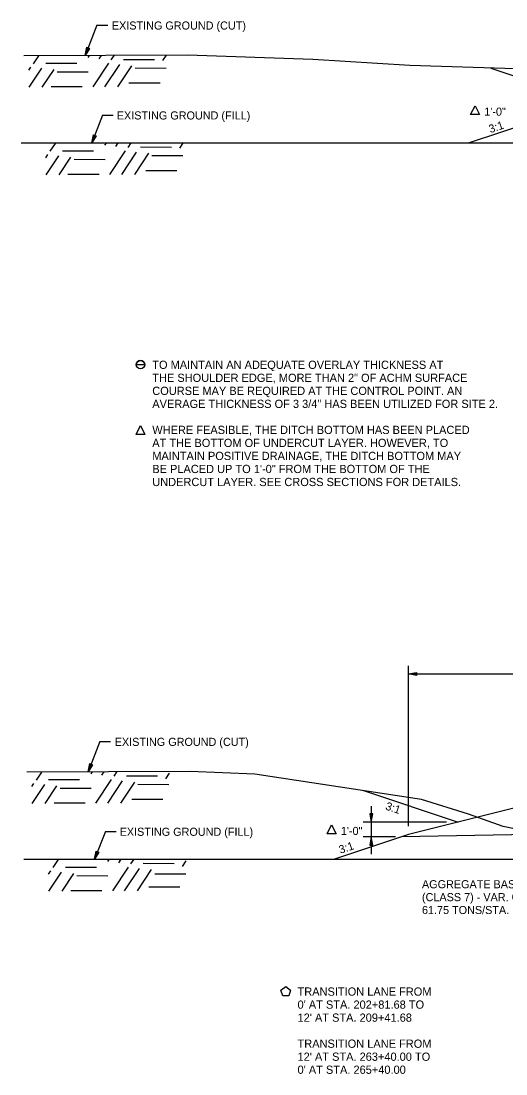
# Model space of a CAD drawing. Extents: x 1398565 to 1398920, y 1968324 to 1968581.
# Drawn here: x 1398565.6 to 1398600.9, y 1968324.5 to 1968401.3 of the extents above; entities that cross this region are included whole.
import ezdxf

# ---------------------------------------------------------------- set-up
doc = ezdxf.new("R2010")
doc.units = 0
for name, color, linetype in [('10', 7, 'Continuous'), ('19', 7, 'Continuous'), ('42', 7, 'Continuous'), ('9', 7, 'Continuous'), ('Default', 7, 'Continuous')]:
    doc.layers.add(name, color=color, linetype=linetype)

msp = doc.modelspace()

# ---------------------------------------------------------------- linework, layer by layer
at = {"layer": '10'}
msp.add_line((1398573.963, 1968376.246), (1398574.574, 1968376.246), dxfattribs=at)
for points in [[(1398598.655, 1968395.138), (1398598.975, 1968394.497), (1398598.334, 1968394.497)], [(1398574.272, 1968371.802), (1398574.592, 1968371.16), (1398573.951, 1968371.16)], [(1398588.201, 1968342.662), (1398588.521, 1968342.021), (1398587.88, 1968342.021)], [(1398584.51, 1968330.615), (1398584.859, 1968330.869), (1398585.208, 1968330.615), (1398585.075, 1968330.204), (1398584.643, 1968330.204)]]:
    msp.add_lwpolyline(points, close=True, dxfattribs=at)
msp.add_circle((1398574.268, 1968376.246), 0.306, dxfattribs=at)
msp.add_arc((1398574.268, 1968376.246), 0.306, 0, 180, dxfattribs=at)
at = {"layer": '19'}
for p, q in [((1398571.097, 1968401.005), (1398570.24, 1968398.803)), ((1398571.097, 1968401.005), (1398571.879, 1968401.005)), ((1398570.24, 1968398.803), (1398570.36, 1968399.4)), ((1398570.556, 1968399.324), (1398570.24, 1968398.803)), ((1398570.284, 1968398.958), (1398570.411, 1968399.38)), ((1398570.509, 1968399.342), (1398570.312, 1968398.947)), ((1398570.36, 1968399.4), (1398570.556, 1968399.324)), ((1398599.796, 1968397.888), (1398607.436, 1968395.342)), ((1398605.586, 1968394.879), (1398598.222, 1968392.424)), ((1398571.498, 1968394.445), (1398570.713, 1968392.425)), ((1398571.498, 1968394.445), (1398572.281, 1968394.445)), ((1398570.713, 1968392.425), (1398570.832, 1968393.022)), ((1398571.028, 1968392.946), (1398570.713, 1968392.425)), ((1398570.757, 1968392.579), (1398570.884, 1968393.002)), ((1398570.981, 1968392.964), (1398570.785, 1968392.569)), ((1398570.832, 1968393.022), (1398571.028, 1968392.946)), ((1398593.795, 1968342.574), (1398593.795, 1968354.28)), ((1398593.795, 1968353.68), (1398594.395, 1968353.785)), ((1398593.795, 1968353.68), (1398617.795, 1968353.68)), ((1398594.395, 1968353.575), (1398593.795, 1968353.68)), ((1398593.955, 1968353.695), (1398594.395, 1968353.73)), ((1398594.395, 1968353.625), (1398593.955, 1968353.665)), ((1398594.395, 1968353.785), (1398594.395, 1968353.575)), ((1398571.306, 1968348.742), (1398570.449, 1968346.54)), ((1398571.306, 1968348.742), (1398572.088, 1968348.742)), ((1398570.449, 1968346.54), (1398570.569, 1968347.138)), ((1398570.765, 1968347.061), (1398570.449, 1968346.54)), ((1398570.493, 1968346.695), (1398570.62, 1968347.118)), ((1398570.718, 1968347.08), (1398570.521, 1968346.684)), ((1398570.569, 1968347.138), (1398570.765, 1968347.061)), ((1398611.795, 1968346.458), (1398593.795, 1968341.958)), ((1398590.516, 1968345.169), (1398597.427, 1968342.866)), ((1398591.195, 1968343.466), (1398590.985, 1968343.466)), ((1398590.985, 1968343.466), (1398591.09, 1968342.866)), ((1398591.04, 1968343.466), (1398591.075, 1968343.026)), ((1398591.09, 1968344.023), (1398591.09, 1968342.748)), ((1398591.09, 1968342.866), (1398591.195, 1968343.466)), ((1398591.105, 1968343.026), (1398591.145, 1968343.466)), ((1398591.09, 1968342.748), (1398591.09, 1968340.542)), ((1398642.795, 1968342.782), (1398593.298, 1968341.792)), ((1398571.707, 1968342.182), (1398570.921, 1968340.162)), ((1398571.707, 1968342.182), (1398572.49, 1968342.182)), ((1398593.795, 1968341.958), (1398588.407, 1968340.162)), ((1398591.09, 1968341.792), (1398590.985, 1968341.192)), ((1398590.985, 1968341.192), (1398591.195, 1968341.192)), ((1398591.075, 1968341.632), (1398591.04, 1968341.192)), ((1398591.195, 1968341.192), (1398591.09, 1968341.792)), ((1398591.145, 1968341.192), (1398591.105, 1968341.632)), ((1398570.921, 1968340.162), (1398571.041, 1968340.759)), ((1398571.237, 1968340.683), (1398570.921, 1968340.162)), ((1398570.965, 1968340.317), (1398571.092, 1968340.739)), ((1398571.19, 1968340.701), (1398570.993, 1968340.306)), ((1398571.041, 1968340.759), (1398571.237, 1968340.683))]:
    msp.add_line(p, q, dxfattribs=at)
at = {"layer": '42'}
for points in [[(1398565.563, 1968392.424), (1398612.06, 1968392.424), (1398636.586, 1968398.534), (1398642.586, 1968398.774)], [(1398615.319, 1968393.236), (1398605.766, 1968396.82), (1398601.609, 1968397.832), (1398593.902, 1968398.071), (1398586.821, 1968398.502), (1398577.688, 1968398.831), (1398565.772, 1968398.786)], [(1398565.772, 1968340.162), (1398612.268, 1968340.162), (1398636.795, 1968346.271), (1398642.795, 1968346.511)], [(1398612.268, 1968340.162), (1398600.713, 1968342.553), (1398598.177, 1968343.459), (1398594.756, 1968344.524), (1398582.596, 1968346.375), (1398577.897, 1968346.568), (1398565.981, 1968346.523)]]:
    msp.add_lwpolyline(points, dxfattribs=at)
at = {"layer": '9'}
for p, q in [((1398566.469, 1968398.203), (1398566.858, 1968398.786)), ((1398570.453, 1968398.652), (1398570.556, 1968398.807)), ((1398571.251, 1968398.564), (1398571.416, 1968398.812)), ((1398572.141, 1968398.476), (1398572.368, 1968398.817)), ((1398575.905, 1968398.442), (1398576.169, 1968398.838)), ((1398566.131, 1968397.731), (1398566.285, 1968397.961)), ((1398567.359, 1968398.246), (1398569.621, 1968398.24)), ((1398570.81, 1968396.514), (1398571.957, 1968398.234)), ((1398571.67, 1968396.519), (1398572.755, 1968398.146)), ((1398572.623, 1968396.524), (1398573.645, 1968398.058)), ((1398573.031, 1968398.518), (1398575.293, 1968398.513)), ((1398573.869, 1968397.892), (1398576.131, 1968397.886)), ((1398566.16, 1968396.488), (1398567.083, 1968397.873)), ((1398567.112, 1968396.493), (1398567.973, 1968397.785)), ((1398568.197, 1968397.62), (1398570.459, 1968397.614)), ((1398567.758, 1968396.541), (1398570.02, 1968396.536)), ((1398573.43, 1968396.814), (1398575.692, 1968396.808)), ((1398567.696, 1968391.812), (1398568.084, 1968392.394)), ((1398568.585, 1968391.854), (1398570.847, 1968391.848)), ((1398571.679, 1968392.261), (1398571.782, 1968392.415)), ((1398572.037, 1968390.122), (1398573.184, 1968391.842)), ((1398572.477, 1968392.172), (1398572.642, 1968392.42)), ((1398572.897, 1968390.127), (1398573.981, 1968391.754)), ((1398573.368, 1968392.085), (1398573.595, 1968392.425)), ((1398574.257, 1968392.127), (1398576.519, 1968392.121)), ((1398577.132, 1968392.05), (1398577.396, 1968392.446)), ((1398567.358, 1968391.339), (1398567.512, 1968391.57)), ((1398567.386, 1968390.096), (1398568.31, 1968391.481)), ((1398568.339, 1968390.101), (1398569.2, 1968391.394)), ((1398569.423, 1968391.228), (1398571.685, 1968391.222)), ((1398573.849, 1968390.132), (1398574.872, 1968391.666)), ((1398575.095, 1968391.501), (1398577.357, 1968391.495)), ((1398574.656, 1968390.422), (1398576.918, 1968390.417)), ((1398568.984, 1968390.15), (1398571.246, 1968390.144)), ((1398566.678, 1968345.941), (1398567.067, 1968346.523)), ((1398570.662, 1968346.39), (1398570.765, 1968346.544)), ((1398571.46, 1968346.301), (1398571.625, 1968346.549)), ((1398572.35, 1968346.213), (1398572.577, 1968346.554)), ((1398576.114, 1968346.033), (1398576.378, 1968346.43)), ((1398566.34, 1968345.468), (1398566.494, 1968345.699)), ((1398567.568, 1968345.983), (1398569.83, 1968345.977)), ((1398571.019, 1968344.251), (1398572.166, 1968345.971)), ((1398571.879, 1968344.256), (1398572.964, 1968345.883)), ((1398572.832, 1968344.261), (1398573.854, 1968345.795)), ((1398573.24, 1968346.256), (1398575.502, 1968346.25)), ((1398566.369, 1968344.225), (1398567.292, 1968345.61)), ((1398567.321, 1968344.23), (1398568.182, 1968345.522)), ((1398568.406, 1968345.357), (1398570.668, 1968345.351)), ((1398574.078, 1968345.63), (1398576.339, 1968345.624)), ((1398567.967, 1968344.279), (1398570.229, 1968344.273)), ((1398573.639, 1968344.551), (1398575.9, 1968344.545)), ((1398567.905, 1968339.549), (1398568.293, 1968340.132)), ((1398568.794, 1968339.591), (1398571.056, 1968339.585)), ((1398571.888, 1968339.998), (1398571.991, 1968340.152)), ((1398572.246, 1968337.859), (1398573.392, 1968339.58)), ((1398572.686, 1968339.909), (1398572.851, 1968340.157)), ((1398573.576, 1968339.822), (1398573.804, 1968340.162)), ((1398574.466, 1968339.864), (1398576.728, 1968339.858)), ((1398577.34, 1968339.641), (1398577.605, 1968340.038)), ((1398567.567, 1968339.076), (1398567.721, 1968339.307)), ((1398567.595, 1968337.833), (1398568.518, 1968339.218)), ((1398568.547, 1968337.839), (1398569.409, 1968339.131)), ((1398569.632, 1968338.965), (1398571.894, 1968338.959)), ((1398573.106, 1968337.864), (1398574.19, 1968339.491)), ((1398574.058, 1968337.869), (1398575.081, 1968339.404)), ((1398575.304, 1968339.092), (1398577.566, 1968339.086)), ((1398574.865, 1968338.16), (1398577.127, 1968338.154)), ((1398569.193, 1968337.887), (1398571.455, 1968337.881))]:
    msp.add_line(p, q, dxfattribs=at)
at = {"layer": 'Default'}
for p, q in [((1398596.583, 1968342.866), (1398590.495, 1968342.866)), ((1398592.862, 1968341.792), (1398590.509, 1968341.792))]:
    msp.add_line(p, q, dxfattribs=at)

# ---------------------------------------------------------------- texts
at = {"layer": '10'}
for s, height, rotation, p in [('EXISTING GROUND (CUT)', 0.59001, 360, (1398572.181, 1968400.694)), ('1\'-0"', 0.59, 360, (1398599.329, 1968394.41)), ('EXISTING GROUND (FILL)', 0.59001, 360, (1398572.54, 1968394.134)), ('3:1', 0.59, 18.49392, (1398599.77, 1968393.135)), ('EXISTING GROUND (CUT)', 0.59001, 360, (1398572.389, 1968348.431)), ('3:1', 0.59, 341.52236, (1398592.078, 1968343.801)), ('EXISTING GROUND (FILL)', 0.59001, 360, (1398572.749, 1968341.871)), ('1\'-0"', 0.59, 360, (1398588.875, 1968341.934)), ('3:1', 0.59, 18.49392, (1398588.842, 1968340.557))]:
    msp.add_text(s, height=height, rotation=rotation, dxfattribs=at).set_placement(p)
at = {"layer": '19'}
for s, p in [('AGGREGATE BASE COURSE', (1398594.788, 1968338.043)), ('(CLASS 7) - VAR. COMPACTED DEPTH', (1398594.788, 1968337.103)), ('61.75 TONS/STA.', (1398594.788, 1968336.163))]:
    msp.add_text(s, height=0.59001, rotation=360, dxfattribs=at).set_placement(p)
at = {"layer": '42'}
for s, p in [('TO MAINTAIN AN ADEQUATE OVERLAY THICKNESS AT', (1398575.127, 1968375.937)), ('THE SHOULDER EDGE, MORE THAN 2" OF ACHM SURFACE', (1398575.127, 1968374.987)), ('COURSE MAY BE REQUIRED AT THE CONTROL POINT. AN', (1398575.127, 1968374.037)), ('AVERAGE THICKNESS OF 3 3/4" HAS BEEN UTILIZED FOR SITE 2.', (1398575.127, 1968373.087)), ('WHERE FEASIBLE, THE DITCH BOTTOM HAS BEEN PLACED', (1398575.127, 1968371.187)), ('AT THE BOTTOM OF UNDERCUT LAYER. HOWEVER, TO', (1398575.127, 1968370.237)), ('MAINTAIN POSITIVE DRAINAGE, THE DITCH BOTTOM MAY', (1398575.127, 1968369.287)), ('BE PLACED UP TO 1\'-0" FROM THE BOTTOM OF THE', (1398575.127, 1968368.337)), ('UNDERCUT LAYER. SEE CROSS SECTIONS FOR DETAILS.', (1398575.127, 1968367.387)), ('TRANSITION LANE FROM', (1398585.717, 1968330.206)), ("0' AT STA. 202+81.68 TO", (1398585.717, 1968329.256)), ("12' AT STA. 209+41.68", (1398585.717, 1968328.306)), ('TRANSITION LANE FROM', (1398585.717, 1968326.406)), ("12' AT STA. 263+40.00 TO", (1398585.717, 1968325.456)), ("0' AT STA. 265+40.00", (1398585.717, 1968324.506))]:
    msp.add_text(s, height=0.6, dxfattribs=at).set_placement(p)

doc.saveas('drawing.dxf')
